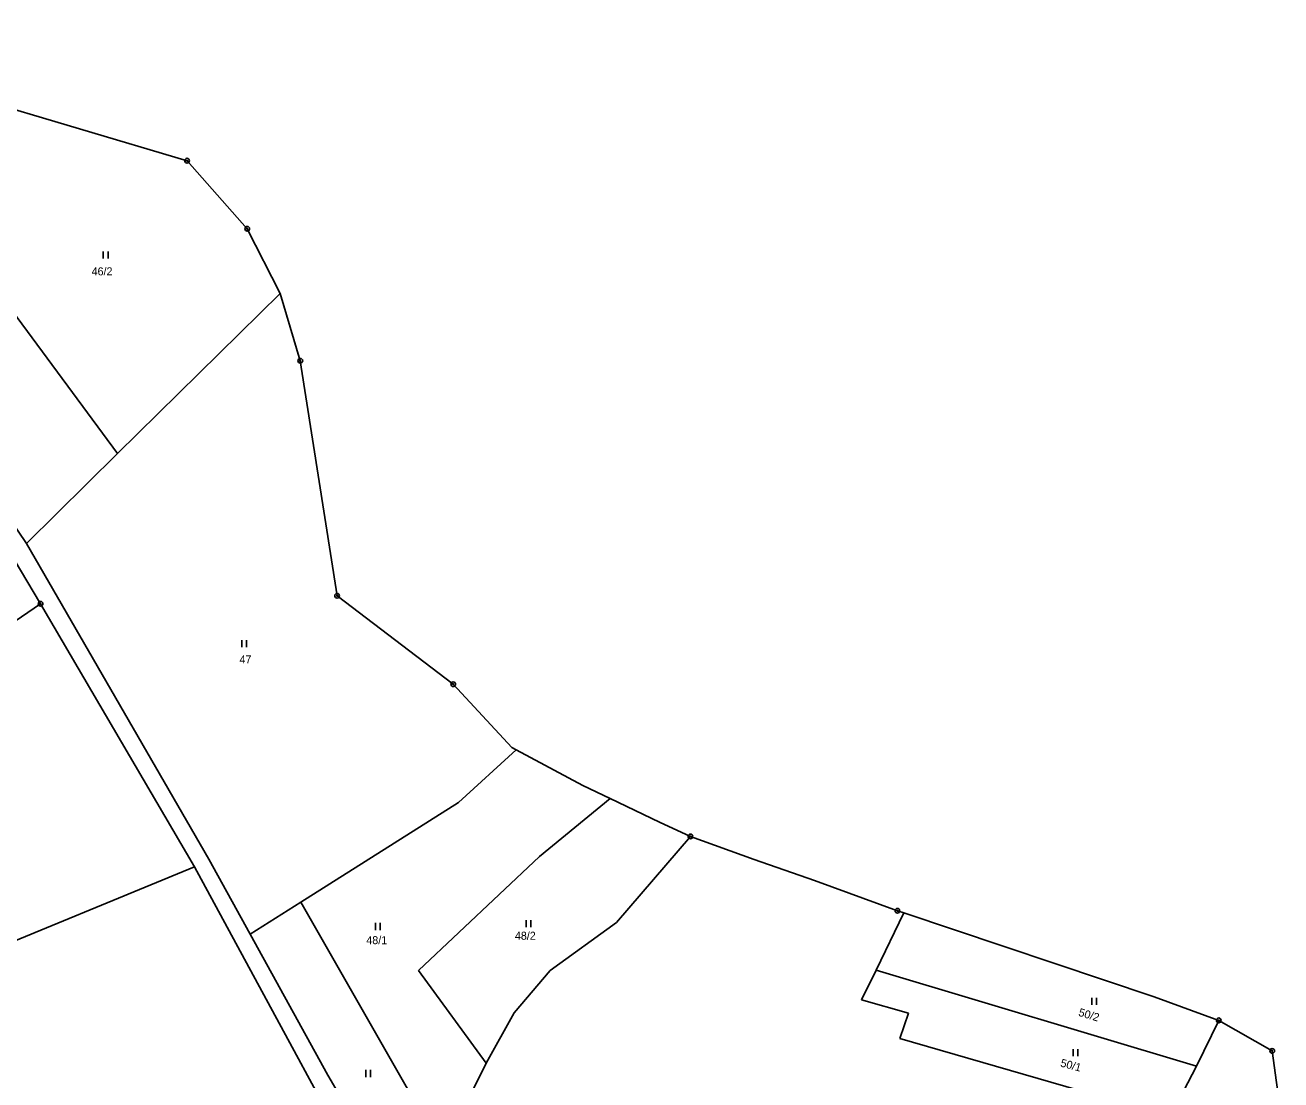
# Model space of a CAD drawing. Extents: x -445050 to -440454, y -1134563 to -1129741.
# Drawn here: x -441582.9 to -441316.2, y -1129965.1 to -1129741.2 of the extents above; entities that cross this region are included whole.
import ezdxf

# ---------------------------------------------------------------- set-up
doc = ezdxf.new("R2010")
doc.units = 0
for name, color, linetype in [('Vrstva 1', 7, 'Continuous'), ('Vrstva 13', 7, 'Continuous'), ('Vrstva 18', 7, 'Continuous'), ('Vrstva 24', 7, 'Continuous'), ('Vrstva 25', 7, 'Continuous'), ('Vrstva 52', 7, 'Continuous'), ('Vrstva 6', 7, 'Continuous')]:
    doc.layers.add(name, color=color, linetype=linetype)

msp = doc.modelspace()

# ---------------------------------------------------------------- linework, layer by layer
at = {"layer": 'Vrstva 1'}
for points in [[(-441591.72, -1129837.97), (-441582.64, -1129851.25)], [(-441582.64, -1129851.25), (-441543.94, -1129918.25)], [(-441585.24, -1129854.64), (-441579.66, -1129864.06)], [(-441579.66, -1129864.06), (-441546.94, -1129919.91)], [(-441546.94, -1129919.91), (-441500.84, -1130004.96)], [(-441543.94, -1129918.25), (-441535.14, -1129934.22)], [(-441535.14, -1129934.22), (-441518.65, -1129964.12)], [(-441334.13, -1129962.23), (-441329.41, -1129952.5)], [(-441339.71, -1129972.97), (-441334.13, -1129962.23)], [(-441518.65, -1129964.12), (-441492.32, -1130009.24)]]:
    msp.add_lwpolyline(points, dxfattribs=at)
at = {"layer": 'Vrstva 13'}
for points in [[(-441594.36, -1129756.43), (-441548.54, -1129769.98)], [(-441548.54, -1129769.98), (-441535.75, -1129784.43)], [(-441535.75, -1129784.43), (-441528.76, -1129798.16)], [(-441528.76, -1129798.16), (-441524.48, -1129812.45)], [(-441524.48, -1129812.45), (-441516.67, -1129862.35)], [(-441516.67, -1129862.35), (-441492, -1129881.15)], [(-441492, -1129881.15), (-441479.58, -1129894.54)], [(-441479.58, -1129894.54), (-441478.61, -1129895.06)], [(-441478.61, -1129895.06), (-441464.46, -1129902.63)], [(-441464.46, -1129902.63), (-441458.68, -1129905.42)], [(-441458.68, -1129905.42), (-441448.22, -1129910.45)], [(-441448.22, -1129910.45), (-441441.62, -1129913.46)], [(-441441.62, -1129913.46), (-441428.07, -1129918.35)], [(-441428.07, -1129918.35), (-441415.24, -1129922.84)], [(-441415.24, -1129922.84), (-441397.66, -1129929.24)], [(-441397.66, -1129929.24), (-441396.28, -1129929.7)], [(-441396.28, -1129929.7), (-441343.12, -1129947.52)], [(-441343.12, -1129947.52), (-441329.41, -1129952.5)], [(-441329.41, -1129952.5), (-441318.04, -1129958.98)], [(-441318.04, -1129958.98), (-441316.2, -1129972.39)]]:
    msp.add_lwpolyline(points, dxfattribs=at)
at = {"layer": 'Vrstva 24'}
for centre, radius in [((-441548.54, -1129769.98), 0.5), ((-441548.54, -1129769.98), 0.1), ((-441535.75, -1129784.43), 0.5), ((-441535.75, -1129784.43), 0.1), ((-441524.48, -1129812.45), 0.5), ((-441524.48, -1129812.45), 0.1), ((-441516.67, -1129862.35), 0.5), ((-441579.66, -1129864.06), 0.5), ((-441579.66, -1129864.06), 0.1), ((-441516.67, -1129862.35), 0.1), ((-441492, -1129881.15), 0.5), ((-441492, -1129881.15), 0.1), ((-441441.62, -1129913.46), 0.5), ((-441441.62, -1129913.46), 0.1), ((-441397.66, -1129929.24), 0.5), ((-441397.66, -1129929.24), 0.1), ((-441329.41, -1129952.5), 0.5), ((-441329.41, -1129952.5), 0.1), ((-441318.04, -1129958.98), 0.5), ((-441318.04, -1129958.98), 0.1)]:
    msp.add_circle(centre, radius, dxfattribs=at)
at = {"layer": 'Vrstva 25'}
for p, q in [((-441566.33, -1129790.75), (-441566.33, -1129789.25)), ((-441565.33, -1129790.75), (-441565.33, -1129789.25)), ((-441536.89, -1129873.29), (-441536.89, -1129871.79)), ((-441535.89, -1129873.29), (-441535.89, -1129871.79)), ((-441476.49, -1129932.7), (-441476.49, -1129931.2)), ((-441475.49, -1129932.7), (-441475.49, -1129931.2)), ((-441508.51, -1129933.33), (-441508.51, -1129931.83)), ((-441507.51, -1129933.33), (-441507.51, -1129931.83)), ((-441356.37, -1129949.24), (-441356.37, -1129947.74)), ((-441355.37, -1129949.24), (-441355.37, -1129947.74)), ((-441360.34, -1129960.13), (-441360.34, -1129958.63)), ((-441359.34, -1129960.13), (-441359.34, -1129958.63)), ((-441510.6, -1129964.53), (-441510.6, -1129963.03)), ((-441509.6, -1129964.53), (-441509.6, -1129963.03))]:
    msp.add_line(p, q, dxfattribs=at)
at = {"layer": 'Vrstva 52'}
msp.add_lwpolyline([(-441594.36, -1129756.43), (-441548.54, -1129769.98), (-441535.75, -1129784.43), (-441528.76, -1129798.16), (-441524.48, -1129812.45), (-441516.67, -1129862.35), (-441492, -1129881.15), (-441479.58, -1129894.54), (-441478.61, -1129895.06), (-441464.46, -1129902.63), (-441458.68, -1129905.42), (-441448.22, -1129910.45), (-441441.62, -1129913.46), (-441428.07, -1129918.35), (-441415.24, -1129922.84), (-441397.66, -1129929.24), (-441396.28, -1129929.7), (-441343.12, -1129947.52), (-441329.41, -1129952.5), (-441318.04, -1129958.98), (-441316.2, -1129972.39)], dxfattribs=at)
at = {"layer": 'Vrstva 6'}
for points in [[(-441630.48, -1129741.2), (-441563.33, -1129832.15)], [(-441528.76, -1129798.16), (-441563.33, -1129832.15)], [(-441563.33, -1129832.15), (-441582.64, -1129851.25)], [(-441579.66, -1129864.06), (-441628.48, -1129897.43)], [(-441490.91, -1129906.26), (-441478.61, -1129895.06)], [(-441524.34, -1129927.39), (-441490.91, -1129906.26)], [(-441458.68, -1129905.42), (-441473.7, -1129917.68)], [(-441441.62, -1129913.46), (-441457.32, -1129931.75)], [(-441473.7, -1129917.68), (-441499.35, -1129941.89)], [(-441546.94, -1129919.91), (-441595.83, -1129939.98)], [(-441535.14, -1129934.22), (-441524.34, -1129927.39)], [(-441524.34, -1129927.39), (-441490.09, -1129987.36)], [(-441402.2, -1129941.84), (-441396.28, -1129929.7)], [(-441457.32, -1129931.75), (-441471.44, -1129941.95)], [(-441499.35, -1129941.89), (-441485.04, -1129961.57)], [(-441471.44, -1129941.95), (-441479.05, -1129950.93)], [(-441405.3, -1129948.18), (-441402.2, -1129941.84)], [(-441334.13, -1129962.23), (-441402.2, -1129941.84)], [(-441405.3, -1129948.18), (-441395.33, -1129951.01)], [(-441479.05, -1129950.93), (-441485.04, -1129961.57)], [(-441395.33, -1129951.01), (-441397.17, -1129956.34)], [(-441359.18, -1129967.31), (-441397.17, -1129956.34)], [(-441485.04, -1129961.57), (-441488.12, -1129967.89)]]:
    msp.add_lwpolyline(points, dxfattribs=at)

# ---------------------------------------------------------------- texts
at = {"layer": 'Vrstva 18'}
for s, p in [('46/2', (-441568.81, -1129794.33)), ('47', (-441537.4, -1129876.72)), ('48/2', (-441478.9, -1129935.39)), ('48/1', (-441510.46, -1129936.33))]:
    msp.add_text(s, height=1.7, dxfattribs=at).set_placement(p)
for s, rotation, p in [('50/2', 343.1475, (-441359.32, -1129951.5)), ('50/1', 345.3534, (-441363.14, -1129962.28))]:
    msp.add_text(s, height=1.7, rotation=rotation, dxfattribs=at).set_placement(p)

doc.saveas('drawing.dxf')
